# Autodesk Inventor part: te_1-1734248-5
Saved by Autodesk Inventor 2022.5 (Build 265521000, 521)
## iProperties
Created: 2024-12
Part Number: te_1-1734248-5
Material: Generic
Document SubType Name: Modeling
Designer: AdminForWorker
Density: 1 g/cm^3
Appearance: Default
Title: te_1-1734248-5
Author: AdminForWorker
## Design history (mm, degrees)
feature "Body1"
feature "Body2"
feature "Body3"
feature "Body4"
feature "Body5"
feature "Body6"
feature "Body7"
feature "Body8"
feature "Body9"
feature "Body10"
feature "Body11"
feature "Body12"
feature "Body13"
feature "Body14"
feature "Body15"
feature "Body16"
feature "Body17"
body "Solid1"
body "Solid2"
body "Solid3"
body "Solid4"
body "Solid5"
body "Solid6"
body "Solid7"
body "Solid8"
body "Solid9"
body "Solid10"
body "Solid11"
body "Solid12"
body "Solid13"
body "Solid14"
body "Solid15"
body "Solid16"
body "Solid17"
